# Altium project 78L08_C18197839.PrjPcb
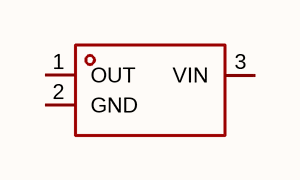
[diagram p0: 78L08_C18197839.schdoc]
1 sheet, 1 parts. Net scope: global (net labels, ports and power ports of the same name join across sheets).

## Sheet 78L08_C18197839.schdoc
size 127 x 101 mm

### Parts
U?  78l08_c18197839  [SOT-89-3_L4.3-W2.3-P1.50-LS4.3-BR]  (value not drawn)

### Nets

Not connected (* = marked no-connect by the designer): U? 1(OUT) 2(GND) 3(VIN)

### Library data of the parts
U? = 78l08_c18197839: 输出极性:正极;工作电压:23V;输出电压:8V;输出电流:100mA;电源纹波抑制比(PSRR):46dB@(120Hz);输出类型:固定;; Manufacturer: TECH PUBLIC(台舟); ManufacturerPart: 78L08; AddInBom: yes; ModelId: 13a61ebef0f84f538eafb98eafc62ef6; ModelTransform: 161.22,177.165,0,0,0,0,-13.11,0,0; Output Configuration: 正极; Voltage - Supply: 23V; Output Voltage: 8V; Output Current: 100mA; Voltage Dropout: 1.7V; standby current: 4mA; Noise: 54uV; Output Type: 固定; Number of Outputs: 1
